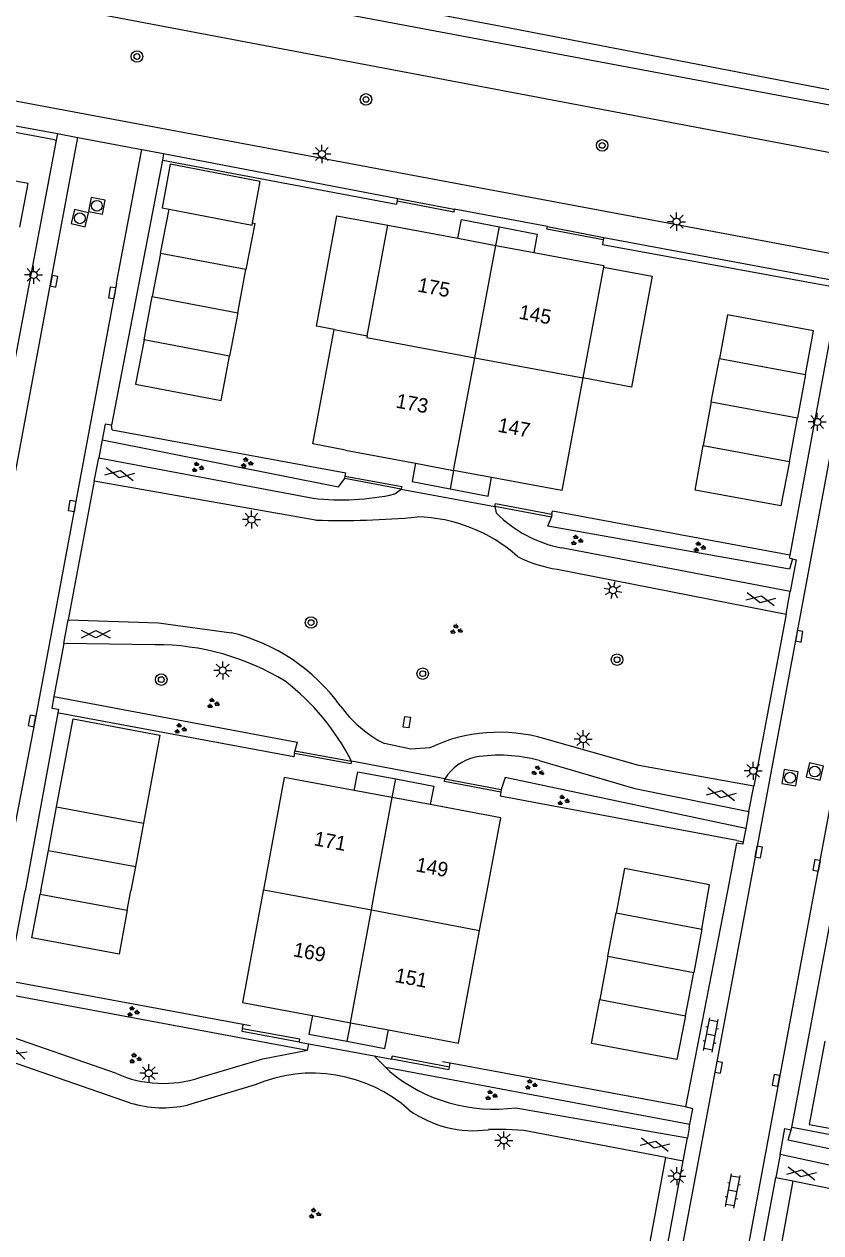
# Model space of a CAD drawing. Extents: x 124000 to 128010, y 398999 to 403000.
# Drawn here: x 126725.4 to 126780.7, y 399476.3 to 399560.1 of the extents above; entities that cross this region are included whole.
import ezdxf

# ---------------------------------------------------------------- set-up
doc = ezdxf.new("R2010")
doc.units = 0
for name, color, linetype in [('gg-afsc-hekwerk', 7, 'Continuous'), ('gg-afsc-muur', 7, 'Continuous'), ('gg-anno-huisnummerreeks BGT', 7, 'Continuous'), ('gg-bbg-bijgebouw', 7, 'Continuous'), ('gg-bbg-hoofdgebouw', 7, 'Continuous'), ('gg-bbg-luifel en loopbrug', 7, 'Continuous'), ('gg-bbg-tussenscheiding', 7, 'Continuous'), ('gg-knt-BGT kruinlijn', 7, 'Continuous'), ('gg-knt-verharding', 7, 'Continuous'), ('gg-knt-verharding nz', 7, 'Continuous'), ('gg-kntw-beschoeiing', 7, 'Continuous'), ('gt-grn-groengrens', 7, 'Continuous'), ('gt-grn-vlakafsluiter', 7, 'Continuous'), ('gt-symb-boom', 7, 'Continuous'), ('gt-symb-gesloten verharding', 7, 'Continuous'), ('gt-symb-groenvak', 7, 'Continuous'), ('gt-symb-klinker verharding', 7, 'Continuous'), ('gt-symb-kolk', 7, 'Continuous'), ('gt-symb-kolk center center', 7, 'Continuous'), ('gt-symb-lichtmast', 7, 'Continuous'), ('gt-symb-rioolschacht', 7, 'Continuous')]:
    doc.layers.add(name, color=color, linetype=linetype)

# ---------------------------------------------------------------- blocks, each defined once
blk = doc.blocks.new('gt0-KOLK')
at = {"layer": 'gt-symb-kolk'}
blk.add_lwpolyline([(0, 0), (0.375, 0), (0.375, 0.4), (-0.375, 0.4), (-0.375, 0), (0, 0)], dxfattribs=at)
blk = doc.blocks.new('gt0-GESVH1')
at = {"layer": 'gt-symb-gesloten verharding'}
for p, q in [((-0.992, -0.261), (0.008, 0.239)), ((0.008, -0.261), (-0.992, 0.239)), ((0.008, 0.239), (1.008, -0.261)), ((1.008, 0.239), (0.008, -0.261))]:
    blk.add_line(p, q, dxfattribs=at)
blk = doc.blocks.new('gt0-GRVAK')
at = {"layer": 'gt-symb-groenvak'}
for p, q in [((-0.11, 0.189), (-0.228, 0.24)), ((-0.182, 0.153), (0.088, 0.153)), ((-0.091, 0.211), (-0.156, 0.322)), ((-0.047, 0.214), (-0.047, 0.393)), ((-0.004, 0.211), (0.061, 0.322)), ((0.015, 0.189), (0.133, 0.24)), ((0.262, -0.052), (0.197, 0.059)), ((0.305, -0.049), (0.305, 0.13)), ((0.349, -0.052), (0.414, 0.059)), ((-0.245, -0.228), (-0.363, -0.177)), ((-0.318, -0.264), (-0.047, -0.264)), ((-0.226, -0.206), (-0.291, -0.095)), ((-0.183, -0.203), (-0.183, -0.024)), ((-0.139, -0.206), (-0.074, -0.095)), ((-0.12, -0.228), (-0.002, -0.177)), ((0.243, -0.074), (0.125, -0.023)), ((0.17, -0.11), (0.441, -0.11)), ((0.368, -0.074), (0.486, -0.023))]:
    blk.add_line(p, q, dxfattribs=at)
blk = doc.blocks.new('gt0-LMAST')
at = {"layer": 'gt-symb-lichtmast'}
for p, q in [((-0.182, 0.173), (-0.447, 0.438)), ((-0.005, 0.246), (-0.005, 0.621)), ((0.172, 0.173), (0.437, 0.438)), ((-0.255, -0.004), (-0.63, -0.004)), ((-0.182, -0.181), (-0.447, -0.446)), ((-0.005, -0.254), (-0.005, -0.629)), ((0.437, -0.446), (0.172, -0.181)), ((0.245, -0.004), (0.62, -0.004))]:
    blk.add_line(p, q, dxfattribs=at)
blk.add_circle((-0.005, -0.004), 0.25, dxfattribs=at)
blk = doc.blocks.new('gt0-KL1')
at = {"layer": 'gt-symb-klinker verharding'}
for p, q in [((-1.15, 0.3), (1.15, 0.3)), ((-1, -0.3), (-1, 0.3)), ((-0.5, 0.3), (-0.5, 0.45)), ((0, -0.3), (0, 0.3)), ((0.5, 0.3), (0.5, 0.45)), ((1, -0.3), (1, 0.3)), ((-1.15, -0.3), (1.15, -0.3)), ((-0.5, -0.45), (-0.5, -0.3)), ((0.5, -0.45), (0.5, -0.3))]:
    blk.add_line(p, q, dxfattribs=at)
blk = doc.blocks.new('gt0-KOLKCC')
at = {"layer": 'gt-symb-kolk center center'}
blk.add_lwpolyline([(-0.375, 0.2), (0.375, 0.2), (0.375, -0.2), (-0.375, -0.2)], close=True, dxfattribs=at)
blk = doc.blocks.new('gt0-BOOM')
at = {"layer": 'gt-symb-boom'}
for radius in [0.4, 0.2]:
    blk.add_circle((0, 0), radius, dxfattribs=at)
blk = doc.blocks.new('gt0-RS')
at = {"layer": 'gt-symb-rioolschacht'}
blk.add_lwpolyline([(-0.5, -0.5), (0.5, -0.5), (0.5, 0.5), (-0.5, 0.5)], close=True, dxfattribs=at)
blk.add_circle((0, 0), 0.375, dxfattribs=at)

msp = doc.modelspace()

# ---------------------------------------------------------------- linework, layer by layer
at = {"layer": 'gg-afsc-hekwerk'}
for p, q in [((126727.472, 399552.105), (126710.947, 399555.185)), ((126734.98, 399550.691), (126751.215, 399547.633)), ((126781.846, 399541.841), (126765.496, 399544.831)), ((126731.468, 399531.998), (126747.689, 399529.011)), ((126778.504, 399523.3), (126762.041, 399526.344)), ((126744.073, 399509.299), (126727.764, 399512.338)), ((126774.83, 399503.487), (126758.398, 399506.581)), ((126740.571, 399490.717), (126724.207, 399493.759)), ((126741.068, 399490.625), (126740.571, 399490.717)), ((126754.932, 399488.049), (126754.407, 399488.147)), ((126771.268, 399485.013), (126754.932, 399488.049)), ((126795.53, 399480.41), (126778.781, 399483.557))]:
    msp.add_line(p, q, dxfattribs=at)
at = {"layer": 'gg-afsc-muur'}
for p, q in [((126751.256, 399547.852), (126751.293, 399548.046)), ((126751.293, 399548.046), (126755.219, 399547.288)), ((126761.685, 399546.085), (126765.592, 399545.34)), ((126765.592, 399545.34), (126765.559, 399545.167)), ((126747.612, 399528.601), (126747.645, 399528.777)), ((126751.535, 399527.873), (126747.612, 399528.601)), ((126761.965, 399525.934), (126758.038, 399526.674)), ((126762, 399526.125), (126761.965, 399525.934)), ((126744.116, 399509.531), (126744.151, 399509.72)), ((126744.151, 399509.72), (126748.076, 399509)), ((126754.565, 399507.769), (126758.481, 399507.025)), ((126758.481, 399507.025), (126758.447, 399506.845)), ((126740.484, 399490.24), (126740.52, 399490.437)), ((126744.456, 399489.511), (126740.484, 399490.24)), ((126744.492, 399489.708), (126740.52, 399490.437)), ((126744.456, 399489.511), (126744.492, 399489.708)), ((126750.877, 399488.327), (126750.914, 399488.524)), ((126754.844, 399487.583), (126750.877, 399488.327)), ((126754.881, 399487.779), (126750.914, 399488.524)), ((126754.844, 399487.583), (126754.881, 399487.779))]:
    msp.add_line(p, q, dxfattribs=at)
for points in [[(126755.219, 399547.288), (126755.181, 399547.095), (126751.256, 399547.852)], [(126765.559, 399545.167), (126761.652, 399545.912), (126761.685, 399546.085)], [(126747.645, 399528.777), (126751.567, 399528.048), (126751.535, 399527.873)], [(126758.038, 399526.674), (126758.074, 399526.865), (126762, 399526.125)], [(126748.076, 399509), (126748.042, 399508.812), (126744.116, 399509.531)], [(126758.447, 399506.845), (126754.531, 399507.588), (126754.565, 399507.769)]]:
    msp.add_lwpolyline(points, dxfattribs=at)
at = {"layer": 'gg-bbg-bijgebouw'}
for p, q in [((126741.207, 399546.342), (126741.745, 399549.224)), ((126734.822, 399544.229), (126734.254, 399541.236)), ((126740.754, 399543.104), (126734.822, 399544.229)), ((126740.187, 399540.112), (126740.754, 399543.104)), ((126733.682, 399538.221), (126734.254, 399541.236)), ((126740.187, 399540.112), (126739.615, 399537.096)), ((126739.615, 399537.096), (126733.682, 399538.221)), ((126773.06, 399533.92), (126773.616, 399536.926)), ((126773.616, 399536.926), (126779.6, 399535.819)), ((126779.6, 399535.819), (126779.045, 399532.813)), ((126773.06, 399533.92), (126772.502, 399530.901)), ((126778.487, 399529.795), (126779.045, 399532.813)), ((126772.502, 399530.901), (126778.487, 399529.795)), ((126727.043, 399502.807), (126727.607, 399505.826)), ((126727.607, 399505.826), (126733.647, 399504.699)), ((126733.647, 399504.699), (126733.084, 399501.681)), ((126726.519, 399500), (126727.043, 399502.807)), ((126733.084, 399501.681), (126732.77, 399500)), ((126726.519, 399500), (126726.478, 399499.782)), ((126726.478, 399499.782), (126732.519, 399498.654)), ((126732.519, 399498.654), (126732.77, 399500)), ((126765.886, 399495.466), (126766.458, 399498.482)), ((126766.458, 399498.482), (126772.41, 399497.353)), ((126772.41, 399497.353), (126771.838, 399494.337)), ((126765.886, 399495.466), (126765.315, 399492.457)), ((126771.267, 399491.327), (126771.838, 399494.337)), ((126765.315, 399492.457), (126771.267, 399491.327))]:
    msp.add_line(p, q, dxfattribs=at)
for points in [[(126741.745, 399549.224), (126735.495, 399550.416), (126734.931, 399547.391), (126735.436, 399547.295)], [(126735.436, 399547.295), (126741.18, 399546.198), (126741.207, 399546.342)]]:
    msp.add_lwpolyline(points, dxfattribs=at)
at = {"layer": 'gg-bbg-hoofdgebouw'}
for p, q in [((126749.162, 399538.518), (126750.599, 399546.189)), ((126750.599, 399546.189), (126755.461, 399545.278)), ((126755.461, 399545.278), (126758.099, 399544.784)), ((126758.099, 399544.784), (126760.737, 399544.29)), ((126765.58, 399543.282), (126764.138, 399535.586)), ((126746.881, 399538.946), (126749.162, 399538.518)), ((126747.676, 399530.582), (126752.535, 399529.671)), ((126752.535, 399529.671), (126755.173, 399529.177)), ((126757.811, 399528.683), (126755.173, 399529.177)), ((126750.915, 399506.476), (126748.276, 399506.967)), ((126753.554, 399505.985), (126750.915, 399506.476)), ((126741.965, 399500.081), (126741.95, 399500)), ((126756.977, 399497.261), (126757.494, 399500)), ((126745.364, 399491.348), (126748.002, 399490.85)), ((126748.002, 399490.85), (126750.64, 399490.352))]:
    msp.add_line(p, q, dxfattribs=at)
for points in [[(126760.737, 399544.29), (126765.598, 399543.38), (126765.58, 399543.282)], [(126747.676, 399530.582), (126745.394, 399531.009), (126746.881, 399538.946)], [(126764.138, 399535.586), (126762.674, 399527.772), (126757.811, 399528.683)], [(126748.276, 399506.967), (126743.415, 399507.872), (126741.965, 399500.081)], [(126757.494, 399500), (126758.452, 399505.073), (126753.554, 399505.985)], [(126741.95, 399500), (126740.51, 399492.264), (126745.364, 399491.348)], [(126750.64, 399490.352), (126755.5, 399489.434), (126756.977, 399497.261)]]:
    msp.add_lwpolyline(points, dxfattribs=at)
at = {"layer": 'gg-bbg-luifel en loopbrug'}
for p, q in [((126734.822, 399544.229), (126735.436, 399547.295)), ((126758.099, 399544.784), (126758.345, 399546.073)), ((126755.173, 399529.177), (126754.927, 399527.888)), ((126750.915, 399506.476), (126751.161, 399507.765)), ((126748.002, 399490.85), (126747.756, 399489.561))]:
    msp.add_line(p, q, dxfattribs=at)
for points in [[(126725.053, 399546.054), (126725.627, 399549.087), (126719.654, 399550.187), (126719.095, 399547.152)], [(126746.881, 399538.946), (126745.642, 399539.175), (126747.059, 399546.843), (126750.599, 399546.189)], [(126741.207, 399546.342), (126741.362, 399546.313), (126740.754, 399543.104)], [(126755.461, 399545.278), (126755.709, 399546.577), (126758.345, 399546.073)], [(126758.345, 399546.073), (126760.982, 399545.568), (126760.737, 399544.29)], [(126765.58, 399543.282), (126768.965, 399542.647), (126767.524, 399534.952), (126764.138, 399535.586)], [(126779.6, 399535.819), (126780.152, 399538.853), (126774.177, 399539.958), (126773.616, 399536.926)], [(126733.682, 399538.221), (126733.089, 399535.148), (126739.032, 399534.021), (126739.615, 399537.096)], [(126778.487, 399529.795), (126777.891, 399526.708), (126771.931, 399527.81), (126772.502, 399530.901)], [(126752.535, 399529.671), (126752.29, 399528.393), (126754.927, 399527.888)], [(126754.927, 399527.888), (126757.563, 399527.384), (126757.811, 399528.683)], [(126727.607, 399505.826), (126728.767, 399511.931), (126734.787, 399510.808), (126733.647, 399504.699)], [(126748.276, 399506.967), (126748.525, 399508.269), (126751.161, 399507.765)], [(126751.161, 399507.765), (126753.798, 399507.26), (126753.554, 399505.985)], [(126772.41, 399497.353), (126772.943, 399500.427), (126767.039, 399501.547), (126766.458, 399498.482)], [(126732.519, 399498.654), (126731.95, 399495.612), (126725.898, 399496.743), (126726.478, 399499.782)], [(126771.267, 399491.327), (126770.661, 399488.29), (126764.738, 399489.414), (126765.315, 399492.457)], [(126745.364, 399491.348), (126745.119, 399490.066), (126747.756, 399489.561)], [(126747.756, 399489.561), (126750.392, 399489.057), (126750.64, 399490.352)], [(126780.936, 399489.583), (126779.854, 399483.8), (126785.841, 399482.707)]]:
    msp.add_lwpolyline(points, dxfattribs=at)
at = {"layer": 'gg-bbg-tussenscheiding'}
for p, q in [((126756.638, 399536.991), (126758.099, 399544.784)), ((126734.254, 399541.236), (126740.187, 399540.112)), ((126755.173, 399529.177), (126756.638, 399536.991)), ((126756.638, 399536.991), (126764.138, 399535.586)), ((126773.06, 399533.92), (126779.045, 399532.813)), ((126749.708, 399500), (126750.915, 399506.476)), ((126727.043, 399502.807), (126733.084, 399501.681)), ((126741.965, 399500.081), (126742.396, 399500)), ((126742.396, 399500), (126749.461, 399498.673)), ((126749.461, 399498.673), (126749.708, 399500)), ((126748.002, 399490.85), (126749.461, 399498.673)), ((126749.461, 399498.673), (126756.977, 399497.261)), ((126765.886, 399495.466), (126771.838, 399494.337))]:
    msp.add_line(p, q, dxfattribs=at)
msp.add_lwpolyline([(126749.162, 399538.518), (126749.139, 399538.396), (126756.638, 399536.991)], dxfattribs=at)
at = {"layer": 'gg-knt-BGT kruinlijn'}
msp.add_lwpolyline([(126787.178, 399550.094), (126703.342, 399565.974), (126686.788, 399569.405), (126682.263, 399572.046), (126679.171, 399572.084)], dxfattribs=at)
at = {"layer": 'gg-knt-verharding'}
for p, q in [((126785.932, 399543.354), (126678.7, 399563.39)), ((126711.02, 399555.588), (126727.67, 399552.542)), ((126727.67, 399552.542), (126727.584, 399552.084)), ((126727.67, 399552.542), (126729.097, 399552.274)), ((126727.584, 399552.084), (126724.121, 399533.649)), ((126727.523, 399543.853), (126729.097, 399552.274)), ((126729.097, 399552.274), (126733.519, 399551.444)), ((126731.78, 399542.152), (126733.519, 399551.444)), ((126733.519, 399551.444), (126735.04, 399551.158)), ((126735.04, 399551.158), (126734.952, 399550.696)), ((126735.04, 399551.158), (126751.293, 399548.046)), ((126734.952, 399550.696), (126731.431, 399532.3)), ((126761.685, 399546.085), (126755.219, 399547.288)), ((126765.592, 399545.34), (126782.023, 399542.289)), ((126719.324, 399500), (126727.523, 399543.853)), ((126781.937, 399541.824), (126778.504, 399523.3)), ((126781.855, 399533.25), (126775.653, 399500)), ((126730.769, 399531.283), (126730.538, 399530.054)), ((126730.23, 399528.415), (126730.538, 399530.054)), ((126730.538, 399530.054), (126745.425, 399527.238)), ((126730.23, 399528.415), (126728.424, 399518.795)), ((126745.595, 399525.719), (126730.23, 399528.415)), ((126751.084, 399527.536), (126751.535, 399527.873)), ((126751.535, 399527.873), (126758.038, 399526.674)), ((126758.038, 399526.674), (126758.123, 399526.218)), ((126778.542, 399520.777), (126762.664, 399523.792)), ((126762.361, 399522.31), (126778.245, 399519.196)), ((126778.245, 399519.196), (126778.542, 399520.777)), ((126778.245, 399519.196), (126776, 399507.254)), ((126728.118, 399517.165), (126728.424, 399518.795)), ((126728.118, 399517.165), (126727.426, 399513.478)), ((126734.464, 399517.079), (126728.118, 399517.165)), ((126727.701, 399512.35), (126725.419, 399500)), ((126754.565, 399507.769), (126748.076, 399509)), ((126775.673, 399505.513), (126776, 399507.254)), ((126775.673, 399505.513), (126775.448, 399504.317)), ((126775.448, 399504.317), (126775.276, 399503.404)), ((126774.175, 399500), (126771.268, 399485.013)), ((126778.641, 399483.583), (126781.717, 399500)), ((126731.761, 399487.322), (126723.02, 399490.357)), ((126745.038, 399488.942), (126745.12, 399489.389)), ((126745.12, 399489.389), (126749.663, 399488.551)), ((126732.733, 399485.282), (126723.8, 399488.362)), ((126749.663, 399488.551), (126750.434, 399487.772)), ((126750.434, 399487.772), (126750.744, 399487.459)), ((126741.386, 399486.545), (126736.688, 399485.142)), ((126759.5, 399484.953), (126771.398, 399482.864)), ((126771.526, 399483.551), (126771.576, 399483.819)), ((126771.526, 399483.551), (126771.398, 399482.864)), ((126778.611, 399483.421), (126778.641, 399483.583)), ((126771.104, 399481.281), (126771.398, 399482.864)), ((126765.494, 399457.77), (126769.901, 399481.509)), ((126769.901, 399481.509), (126771.104, 399481.281)), ((126777.834, 399481.703), (126777.54, 399480.122)), ((126786.322, 399479.87), (126777.834, 399481.703)), ((126778.728, 399479.879), (126776.998, 399470.565)), ((126777.54, 399480.122), (126778.728, 399479.879))]:
    msp.add_line(p, q, dxfattribs=at)
for points in [[(126731.78, 399542.152), (126726.09, 399511.758), (126723.845, 399500)], [(126780.221, 399500), (126786.183, 399531.789), (126786.367, 399532.624)], [(126731.431, 399532.3), (126730.976, 399532.388), (126730.769, 399531.283)], [(126778.504, 399523.3), (126778.469, 399523.11), (126778.691, 399523.048)], [(126778.691, 399523.048), (126778.956, 399522.975), (126778.542, 399520.777)], [(126728.424, 399518.795), (126734.676, 399518.607), (126739.763, 399517.908)], [(126727.426, 399513.478), (126727.277, 399512.685), (126727.747, 399512.596), (126727.701, 399512.35)], [(126753.523, 399509.932), (126752.192, 399509.828), (126750.364, 399510.22)], [(126776, 399507.254), (126768.029, 399508.691), (126761.5, 399510.549)], [(126761.101, 399509.041), (126767.757, 399507.109), (126775.673, 399505.513)], [(126775.276, 399503.404), (126775.244, 399503.232), (126774.816, 399503.303), (126774.175, 399500)], [(126723.72, 399493.864), (126724.272, 399493.796), (126725.419, 399500)], [(126775.653, 399500), (126765.447, 399445.474), (126759.845, 399415.181), (126756.229, 399396.251), (126755.792, 399396.019)], [(126760.439, 399394.142), (126761.261, 399398.757), (126769.917, 399444.619), (126780.221, 399500)], [(126737.558, 399487.041), (126741.917, 399488.341), (126745.038, 399488.942)], [(126771.576, 399483.819), (126771.771, 399484.873), (126771.268, 399485.013)], [(126769.901, 399481.509), (126760.034, 399483.378), (126758.808, 399483.44), (126757.582, 399483.432)], [(126777.834, 399481.703), (126778.171, 399483.52), (126778.611, 399483.421)], [(126778.728, 399479.879), (126786.016, 399478.391), (126791.862, 399476.621)]]:
    msp.add_lwpolyline(points, dxfattribs=at)
for centre, radius, start, end in [((126747.367, 399544.235), 17.107, 263.48068, 282.54809), ((126747.261, 399584.496), 58.8, 268.37677, 275.25984), ((126752.408, 399515.127), 10.819, 48.31896, 88.71061), ((126764.412, 399532.527), 8.908, 225.08982, 258.68403), ((126763.684, 399531.072), 8.861, 242.56823, 261.41124), ((126736.619, 399505.078), 13.21, 36.03099, 76.23184), ((126734.49, 399499.89), 17.189, 58.49327, 90.08687), ((126733.547, 399501.622), 16.295, 26.92152, 52.47178), ((126754.285, 399517.886), 8.611, 215.81056, 242.91293), ((126758.327, 399499.702), 11.302, 73.69295, 115.1528), ((126757.395, 399506.036), 3.319, 102.49887, 148.52001), ((126758.35, 399499.018), 10.393, 74.65333, 99.26536), ((126735.03, 399494.819), 8.178, 246.44163, 288.00808), ((126745.354, 399477.195), 10.157, 48.43024, 112.99413), ((126757.999, 399496.258), 11.404, 230.49431, 277.56305), ((126734.977, 399492.752), 7.8, 253.27616, 282.6692), ((126756.545, 399490.993), 7.632, 234.31828, 277.81072)]:
    msp.add_arc(centre, radius, start, end, dxfattribs=at)
at = {"layer": 'gg-knt-verharding nz'}
for p, q in [((126766.682, 399457.476), (126771.104, 399481.281)), ((126773.103, 399456.23), (126777.54, 399480.122))]:
    msp.add_line(p, q, dxfattribs=at)
at = {"layer": 'gg-kntw-beschoeiing'}
for p, q in [((126758.462, 399559.96), (126740.77, 399563.378)), ((126814.862, 399549.063), (126758.462, 399559.96))]:
    msp.add_line(p, q, dxfattribs=at)
at = {"layer": 'gt-grn-groengrens'}
for p, q in [((126723.549, 399492.953), (126745.038, 399488.942)), ((126744.456, 399489.511), (126745.12, 399489.389)), ((126749.663, 399488.551), (126750.877, 399488.327)), ((126750.434, 399487.772), (126771.576, 399483.819))]:
    msp.add_line(p, q, dxfattribs=at)
for points in [[(126679.888, 399575.899), (126683.061, 399575.383), (126687.279, 399572.619), (126691.934, 399571.31), (126814.728, 399548.258), (126867.774, 399538.33), (127022.231, 399507.612), (127025.36, 399507.675), (127027.276, 399508.355), (127030.476, 399511.716), (127030.741, 399513.207)], [(126730.769, 399531.283), (126747.181, 399528.028), (126747.612, 399528.601)], [(126778.691, 399523.048), (126778.491, 399522.326), (126761.706, 399525.312), (126761.965, 399525.934)], [(126727.426, 399513.478), (126744.3, 399510.309), (126744.151, 399509.72)], [(126775.448, 399504.317), (126758.742, 399507.876), (126758.481, 399507.025)], [(126795.446, 399479.95), (126795.252, 399479.152), (126778.395, 399482.702), (126778.611, 399483.421)]]:
    msp.add_lwpolyline(points, dxfattribs=at)
at = {"layer": 'gt-grn-vlakafsluiter'}
for p, q in [((126727.472, 399552.105), (126727.584, 399552.084)), ((126734.98, 399550.691), (126734.952, 399550.696)), ((126751.256, 399547.852), (126751.215, 399547.633)), ((126765.559, 399545.167), (126765.496, 399544.831)), ((126731.468, 399531.998), (126731.431, 399532.3)), ((126747.645, 399528.777), (126747.689, 399529.011)), ((126762, 399526.125), (126762.041, 399526.344)), ((126727.764, 399512.338), (126727.701, 399512.35)), ((126744.116, 399509.531), (126744.073, 399509.299)), ((126758.447, 399506.845), (126758.398, 399506.581)), ((126774.83, 399503.487), (126775.276, 399503.404)), ((126740.52, 399490.437), (126740.571, 399490.717)), ((126754.881, 399487.779), (126754.932, 399488.049)), ((126778.781, 399483.557), (126778.641, 399483.583))]:
    msp.add_line(p, q, dxfattribs=at)

# ---------------------------------------------------------------- block references
at = {"layer": 'gt-symb-boom'}
for p in [(126733.19, 399557.887), (126749.089, 399554.911), (126765.483, 399551.722), (126745.274, 399518.615), (126766.516, 399516.04), (126734.876, 399514.655), (126753.024, 399515.07)]:
    msp.add_blockref('gt0-BOOM', p, dxfattribs=at)
at = {"layer": 'gt-symb-gesloten verharding'}
for p, rotation in [((126731.99, 399528.922), -11.242525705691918), ((126776.483, 399520.248), -11.242525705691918), ((126773.741, 399506.721), -11.186329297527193), ((126724.531, 399488.896), -18.416834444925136), ((126769.14, 399482.402), -11.950647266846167), ((126779.317, 399480.407), -11.13011107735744)]:
    msp.add_blockref('gt0-GESVH1', p, dxfattribs=dict(at, rotation=rotation))
msp.add_blockref('gt0-GESVH1', (126730.327, 399517.821), dxfattribs=at)
at = {"layer": 'gt-symb-groenvak'}
for p in [(126740.795, 399529.689), (126737.378, 399529.379), (126763.701, 399524.317), (126772.218, 399523.846), (126738.451, 399513), (126736.177, 399511.242), (126762.762, 399506.272), (126732.894, 399491.613), (126733.048, 399488.364), (126760.516, 399486.554), (126757.748, 399485.809), (126745.504, 399477.611)]:
    msp.add_blockref('gt0-GRVAK', p, dxfattribs=at)
for p, rotation in [((126755.344, 399518.122), -9.321060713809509), ((126760.988, 399508.309), -16.20518537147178)]:
    msp.add_blockref('gt0-GRVAK', p, dxfattribs=dict(at, rotation=rotation))
at = {"layer": 'gt-symb-klinker verharding'}
for p, rotation in [((126773.035, 399489.996), 79.3873904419), ((126774.55, 399479.177), 79.39794170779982)]:
    msp.add_blockref('gt0-KL1', p, dxfattribs=dict(at, rotation=rotation))
at = {"layer": 'gt-symb-kolk'}
for p, rotation in [((126727.233, 399542.336), -100.60205829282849), ((126731.668, 399541.462), 80.7920309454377), ((126778.961, 399517.705), -100.54573436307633), ((126726.09, 399511.758), 79.39794170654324), ((126776.16, 399502.726), -100.54573436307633), ((126780.564, 399501.724), 79.39794170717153), ((126773.383, 399487.796), -100.54573436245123), ((126777.748, 399486.815), 79.45426563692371)]:
    msp.add_blockref('gt0-KOLK', p, dxfattribs=dict(at, rotation=rotation))
at = {"layer": 'gt-symb-kolk center center'}
for p, rotation in [((126728.687, 399526.71), -99.61302586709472), ((126751.919, 399511.705), 80.3304947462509)]:
    msp.add_blockref('gt0-KOLKCC', p, dxfattribs=dict(at, rotation=rotation))
at = {"layer": 'gt-symb-lichtmast'}
for p in [(126746.036, 399551.129), (126770.658, 399546.434), (126726.011, 399542.738), (126780.415, 399532.536), (126741.147, 399525.759), (126739.145, 399515.3), (126764.176, 399510.523), (126775.978, 399508.333), (126734.015, 399487.348), (126758.657, 399482.692), (126770.682, 399480.206)]:
    msp.add_blockref('gt0-LMAST', p, dxfattribs=at)
at = {"layer": 'gt-symb-lichtmast', "rotation": -148.58402124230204}
msp.add_blockref('gt0-LMAST', (126766.23, 399520.857), dxfattribs=at)
at = {"layer": 'gt-symb-rioolschacht'}
for p, rotation in [((126730.406, 399547.53), 78.70129979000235), ((126729.224, 399546.665), 166.8808553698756), ((126778.523, 399507.851), 80.67893928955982), ((126780.244, 399508.28), 75.93596328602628)]:
    msp.add_blockref('gt0-RS', p, dxfattribs=dict(at, rotation=rotation))

# ---------------------------------------------------------------- texts
at = {"layer": 'gg-anno-huisnummerreeks BGT'}
for s, rotation, p in [('175', 349.4, (126752.62, 399541.586)), ('145', 349.4, (126759.654, 399539.707)), ('173', 349.4, (126751.112, 399533.537)), ('147', 349.4, (126758.185, 399531.863)), ('171', 349.5, (126745.422, 399503.168)), ('149', 349.3, (126752.495, 399501.362)), ('169', 349.5, (126743.989, 399495.468)), ('151', 349.3, (126751.046, 399493.683))]:
    msp.add_text(s, height=1, rotation=rotation, dxfattribs=at).set_placement(p)

doc.saveas('drawing.dxf')
